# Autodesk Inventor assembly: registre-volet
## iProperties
Author: chr
Created: 2001-06
Part Number: registre-volet
Document SubType Name: Assemblage
Designer: chr
Control State: 0
Master: False
Checked Out: False
PropertySet Name: Design Tracking Control
Shininess: 21.0
PropertySet Name: _Private Model Information
Length Units: 11269
Angle Units: 11286
Time Units: 11279
Mass Units: 11290
Length Display Precision: 3
Angle Display Precision: 2
Compacted: False
Density: 0.0
Volumn: 0.0
Area: 0.0
PropertySet Name: Model Information
